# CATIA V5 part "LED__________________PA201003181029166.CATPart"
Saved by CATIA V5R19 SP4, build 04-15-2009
Part number: LED__________________PA201003181029166
Bounding box of the stored display mesh (mm): x -2.895 to 2.894, y -2.5 to 2.9, z -10 to 8.71
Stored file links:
  E:\CadInnWork\1\LED__________________PA201003181029166.CATPart
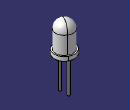
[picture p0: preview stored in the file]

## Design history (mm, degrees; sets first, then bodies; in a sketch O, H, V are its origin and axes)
Parameters
  Update = false
  PDM_version = "A"
  PDM_iteration = 1
  PDM_owner = "moren                    "
  PDM_comment = ""
  PDM_partnumber = "PA002170EA6A57201003181029160006"
Body1 (main body)
  Sketch1 on yz-plane, origin (0, 0, 0), H (0, 1, 0), V (0, 0, 1)
    axis line L1 (0, 64.2413) -> (0, -58.0007)
    point P1 (0, 64.2413)
    line L2 (0, 0) -> (2.9, 0)
    line L3 (2.9, 0) -> (2.9, 1.14)
    line L4 (2.9, 1.14) -> (2.5, 1.14)
    line L5 (2.5, 1.14) -> (2.5, 6.21)
    arc A1 centre (0, 6.21) radius 2.5 from (2.5, 6.21) to (0, 8.71) ccw
    point P7 (0, 6.21)
    point P8 (0, 8.71)
    "Radius" L3 L1 = 2.9
    "Radius" L5 L1 = 2.5
    length L3 = 1.14
    distance L2 P8 = 8.71
    coincidence: P1 V, P8 V, P7 L1
    vertical: L1 V, L3 V, L5 V
    horizontal: L2 H, L4 H
    tangency: A1 L5
  Shaft1: profile Sketch1, axis Sketch1.L1, angle 360
  Sketch2 on yz-plane, origin (0, 0, 0), H (0, 1, 0), V (0, 0, 1)
    line L1 (-4.2366, 3.4966) -> (-2.5, 3.4966)
    line L2 (-2.5, 3.4966) -> (-2.5, -3.9423)
    line L3 (-2.5, -3.9423) -> (-4.2366, -3.9423)
    line L4 (-4.2366, -3.9423) -> (-4.2366, 3.4966)
    reference intersected line E1 through (0, 0) direction (0, 1) from zx-plane
    distance E1 L2 = 2.5
    horizontal: L1 H, L3 H
    vertical: L2 V, L4 V
  Pocket1: profile Sketch2, direction (-1, 0, 0), length 20, mirrored extent
  Sketch3 on face of Shaft1 from Sketch1.L2, origin (0, 0, 0), H (1, 0, 0), V (0, -1, 0)
    line L1 (-0.25, 1.52) -> (0.25, 1.52)
    line L2 (0.25, 1.52) -> (0.25, 1.02)
    line L3 (0.25, 1.02) -> (-0.25, 1.02)
    line L4 (-0.25, 1.02) -> (-0.25, 1.52)
    construction line L5 (0, 1.7254) -> (0, -1.3591)
    reference intersected line E1 through (0, 0) direction (0, 1) from yz-plane
    construction line L6 (1.5543, 1.27) -> (-1.1509, 1.27)
    reference intersected line E2 through (0, 0) direction (1, 0) from zx-plane
    length L4 = 0.5
    length L1 = 0.5
    distance E2 L6 = 1.27
    horizontal: L1 H, L3 H, L6 H
    vertical: L2 V, L4 V, L5 V
    symmetry: L2 L4 L5, L2 L4 E1, L3 L1 L6
  Pad1: profile Sketch3, direction (0, 0, -1), length 10
  Mirror1: of Pad1, about zx-plane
